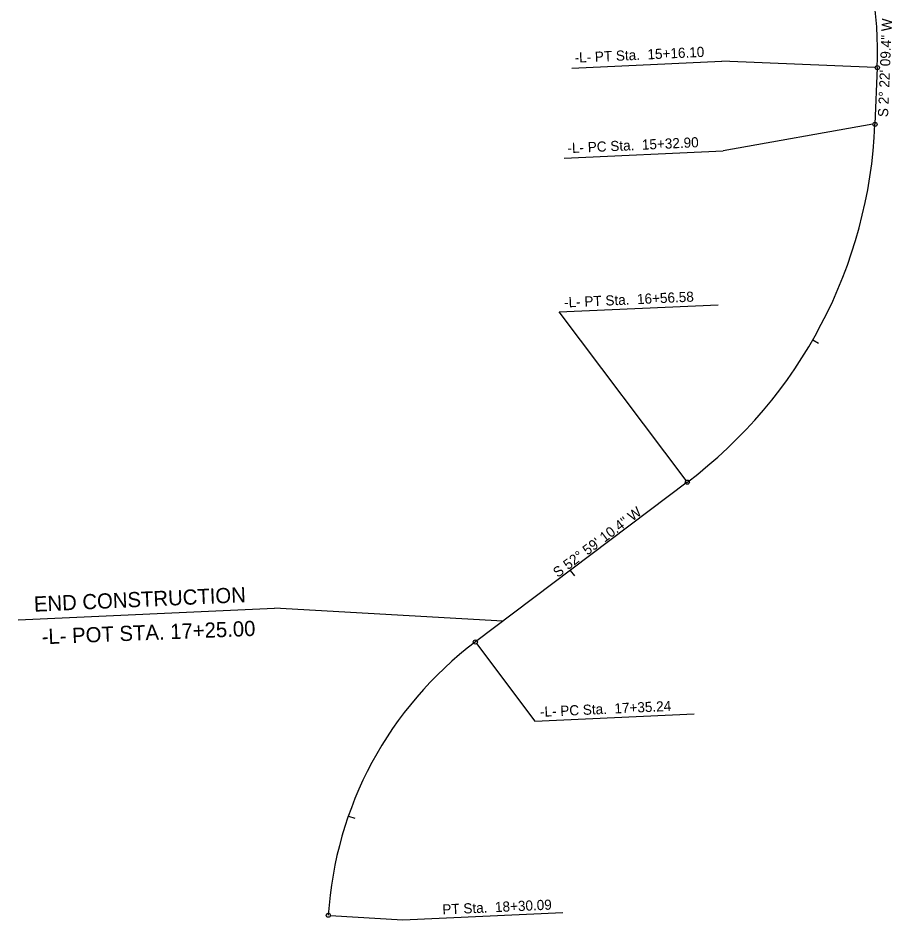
# Model space of a CAD drawing. Extents: x 1191189 to 1191812, y 892693 to 893370.
# Drawn here: x 1191472 to 1191730.9, y 892693.2 to 892960.4 of the extents above; entities that cross this region are included whole.
import ezdxf

# ---------------------------------------------------------------- set-up
doc = ezdxf.new("R2010")
doc.units = 0
for name, color, linetype in [('Prop Horizontal Alignment', 7, 'Continuous'), ('Prop Horizontal Alignment Direction Label', 7, 'Continuous'), ('Prop Horizontal Alignment Station Label', 7, 'Continuous'), ('Prop Horizontal Alignment Tick Small', 7, 'Continuous'), ('Prop Leader Line Medium', 7, 'Continuous')]:
    doc.layers.add(name, color=color, linetype=linetype)

msp = doc.modelspace()

# ---------------------------------------------------------------- linework, layer by layer
at = {"layer": 'Prop Horizontal Alignment'}
for p, q in [((1191726.57, 892945.72), (1191725.88, 892928.93)), ((1191670.28, 892822.93), (1191607.47, 892775.58))]:
    msp.add_line(p, q, dxfattribs=at)
for centre, radius, start, end in [((1191616.66, 892950.27), 110, 357.6307, 47.4533), ((1191586, 892934.72), 140, 307.0138, 357.6307), ((1191673.69, 892687.75), 110, 127.0138, 176.4185)]:
    msp.add_arc(centre, radius, start, end, dxfattribs=at)
at = {"layer": 'Prop Horizontal Alignment Station Label'}
for p, q in [((1191636.02, 892945.59), (1191680.47, 892947.63)), ((1191725.97, 892945.75), (1191680.47, 892947.63)), ((1191725.28, 892928.96), (1191680.89, 892921.04)), ((1191633.77, 892918.89), (1191680.89, 892921.04)), ((1191632.27, 892873.35), (1191679.4, 892875.5)), ((1191669.92, 892823.41), (1191632.27, 892873.35)), ((1191607.83, 892775.1), (1191625.12, 892752.16)), ((1191625.12, 892752.16), (1191672.3, 892754.32)), ((1191564.5, 892694.58), (1191585.94, 892693.24)), ((1191585.94, 892693.24), (1191633.41, 892695.41))]:
    msp.add_line(p, q, dxfattribs=at)
for centre in [(1191726.57, 892945.72), (1191725.88, 892928.93), (1191670.28, 892822.93), (1191607.47, 892775.58), (1191563.9, 892694.62)]:
    msp.add_circle(centre, 0.6, dxfattribs=at)
at = {"layer": 'Prop Horizontal Alignment Tick Small'}
for p, q in [((1191707.45, 892865.08), (1191709.18, 892864.09)), ((1191635.61, 892796.79), (1191636.81, 892795.2)), ((1191569.84, 892724.02), (1191571.73, 892723.36))]:
    msp.add_line(p, q, dxfattribs=at)
at = {"layer": 'Prop Leader Line Medium'}
for p in [(1191471.97, 892782.1), (1191615.64, 892781.74)]:
    msp.add_line(p, (1191548, 892785.58), dxfattribs=at)

# ---------------------------------------------------------------- texts
at = {"layer": 'Prop Horizontal Alignment Direction Label'}
for s, rotation, p in [('S 2%%d 22\' 09.4" W', 87.6307, (1191729.74, 892931.01)), ('S 52%%d 59\' 10.4" W', 37.0138, (1191631.91, 892794.54))]:
    msp.add_text(s, height=3, rotation=rotation, dxfattribs=at).set_placement(p)
at = {"layer": 'Prop Horizontal Alignment Station Label'}
for s, p in [('-L- PT Sta.  15+16.10', (1191636.93, 892947.17)), ('-L- PC Sta.  15+32.90', (1191634.83, 892920.38)), ('-L- PT Sta.  16+56.58', (1191633.83, 892874.66)), ('-L- PC Sta.  17+35.24', (1191626.69, 892753.39)), ('PT Sta.  18+30.09', (1191597.76, 892694.84))]:
    msp.add_text(s, height=3, rotation=2.6195, dxfattribs=at).set_placement(p)
at = {"layer": 'Prop Leader Line Medium'}
for s, rotation, p in [('END CONSTRUCTION', 2.5982, (1191476.77, 892784.54)), ('-L- POT STA. 17+25.00', 2.2753, (1191479.05, 892774.89))]:
    msp.add_text(s, height=4.5, rotation=rotation, dxfattribs=at).set_placement(p)

doc.saveas('drawing.dxf')
